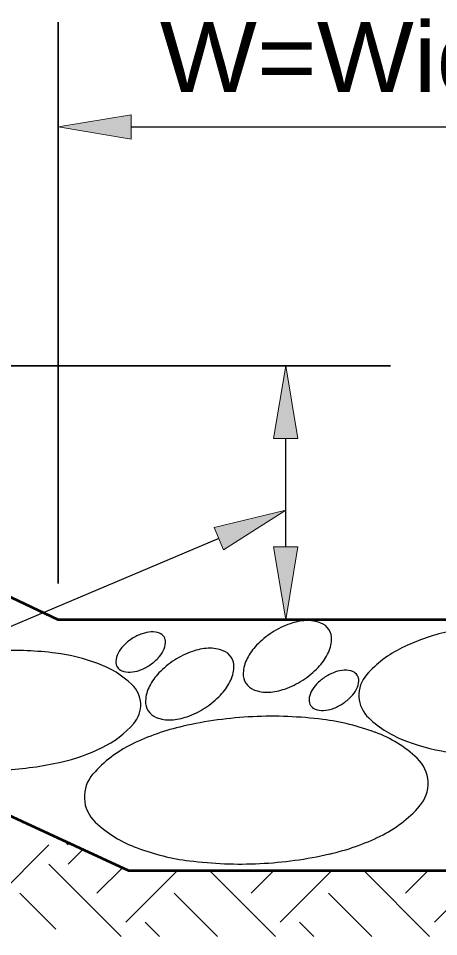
# Model space of a CAD drawing. Extents: x 72.6 to 107.3, y 36.1 to 58.1.
# Drawn here: x 96.33 to 97.053, y 37.866 to 39.443 of the extents above; entities that cross this region are included whole.
import ezdxf

# ---------------------------------------------------------------- set-up
doc = ezdxf.new("R2010")
doc.units = 0
doc.header["$LTSCALE"] = 0.053
for name, color, linetype, lineweight in [('1', 7, 'Continuous', 35), ('3', 7, 'Continuous', 13), ('4', 7, 'Continuous', 25), ('6', 7, 'Continuous', 13)]:
    doc.layers.add(name, color=color, linetype=linetype, lineweight=lineweight)

msp = doc.modelspace()

# ---------------------------------------------------------------- hatches: boundary and pattern name
at = {"layer": '1'}
for points in [[(96.52392, 39.2355), (96.52392, 39.27717), (96.39892, 39.25625), (96.39892, 39.25625)], [(96.81067, 38.72125), (96.769, 38.72125), (96.78983, 38.84625), (96.78983, 38.84625)], [(96.81067, 38.53542), (96.769, 38.53542), (96.78983, 38.41042), (96.78983, 38.41042)]]:
    msp.add_hatch(color=256, dxfattribs=at).paths.add_polyline_path(points)
at = {"layer": '3'}
msp.add_hatch(color=256, dxfattribs=at).paths.add_polyline_path([(96.66658, 38.56892), (96.68283, 38.53058), (96.78983, 38.59842), (96.78983, 38.59842)])

# ---------------------------------------------------------------- linework, layer by layer
at = {"layer": '1'}
for p, q in [((96.39892, 38.47283), (96.39892, 39.43633)), ((95.54108, 38.84625), (96.96983, 38.84625))]:
    msp.add_line(p, q, dxfattribs=at)
at = {"layer": '1', "lineweight": 25}
for p, q in [((96.52392, 39.25633), (97.34317, 39.25633)), ((96.78983, 38.53542), (96.78983, 38.72125)), ((96.28842, 37.92967), (96.38258, 38.02375)), ((96.28842, 37.92967), (96.38258, 38.02375)), ((96.41575, 38.02375), (96.40833, 38.03117)), ((96.41575, 38.02375), (96.40833, 38.03117)), ((96.41575, 37.99058), (96.44108, 38.016)), ((96.41575, 37.99058), (96.44108, 38.016)), ((96.50675, 37.86642), (96.38258, 37.99058)), ((96.50675, 37.86642), (96.38258, 37.99058)), ((96.46542, 37.94092), (96.50917, 37.98458)), ((96.46542, 37.94092), (96.50917, 37.98458)), ((96.51517, 37.89117), (96.60367, 37.97967)), ((96.51517, 37.89117), (96.60367, 37.97967)), ((96.77192, 37.86642), (96.65867, 37.97967)), ((96.77192, 37.86642), (96.65867, 37.97967)), ((96.73058, 37.94092), (96.76942, 37.97967)), ((96.73058, 37.94092), (96.76942, 37.97967)), ((96.78033, 37.89117), (96.86883, 37.97967)), ((96.78033, 37.89117), (96.86883, 37.97967)), ((97.03708, 37.86642), (96.92383, 37.97967)), ((97.03708, 37.86642), (96.92383, 37.97967)), ((96.99575, 37.94092), (97.03458, 37.97967)), ((96.99575, 37.94092), (97.03458, 37.97967)), ((97.0455, 37.89117), (97.134, 37.97967)), ((97.0455, 37.89117), (97.134, 37.97967)), ((96.3945, 37.87925), (96.33283, 37.94092)), ((96.3945, 37.87925), (96.33283, 37.94092)), ((96.6725, 37.86642), (96.598, 37.94092)), ((96.6725, 37.86642), (96.598, 37.94092)), ((96.93767, 37.86642), (96.86317, 37.94092)), ((96.93767, 37.86642), (96.86317, 37.94092)), ((96.57308, 37.86642), (96.54833, 37.89117)), ((96.57308, 37.86642), (96.54833, 37.89117)), ((96.83825, 37.86642), (96.8135, 37.89117)), ((96.83825, 37.86642), (96.8135, 37.89117))]:
    msp.add_line(p, q, dxfattribs=at)
at = {"layer": '1', "lineweight": 13}
msp.add_line((96.76808, 38.41042), (96.60983, 38.41042), dxfattribs=at)
for points in [[(96.52392, 39.2355), (96.52392, 39.27717), (96.39892, 39.25625), (96.39892, 39.25625)], [(96.81067, 38.72125), (96.769, 38.72125), (96.78983, 38.84625), (96.78983, 38.84625)], [(96.81067, 38.53542), (96.769, 38.53542), (96.78983, 38.41042), (96.78983, 38.41042)]]:
    msp.add_lwpolyline(points, close=True, dxfattribs=at)
at = {"layer": '1', "lineweight": 53}
for points in [[(94.3185, 38.997), (96.51967, 37.97967), (97.50133, 37.97967), (99.23892, 38.94783)], [(94.3185, 38.997), (96.51967, 37.97967), (97.50133, 37.97967), (99.23892, 38.94783)], [(98.934, 38.77792), (98.19075, 38.77792), (97.43333, 38.41042), (96.39892, 38.41042), (95.47858, 38.84625), (94.64467, 38.84625)]]:
    msp.add_lwpolyline(points, dxfattribs=at)
at = {"layer": '3'}
msp.add_lwpolyline([(96.66658, 38.56892), (96.68283, 38.53058), (96.78983, 38.59842), (96.78983, 38.59842)], close=True, dxfattribs=at)
at = {"layer": '3', "lineweight": 25}
msp.add_lwpolyline([(96.67475, 38.54975), (95.617, 38.10283), (95.20167, 38.10283)], dxfattribs=at)
at = {"layer": '4'}
for centre, radius, start, end in [((96.84646, 38.26402), 0.14793, 109.47631, 122.81482), ((96.82963, 38.31165), 0.09739, 93.02881, 109.47763), ((96.82776, 38.34713), 0.06186, 68.73244, 93.05444), ((96.83971, 38.37788), 0.02887, 32.82904, 68.71961), ((96.57082, 38.30801), 0.08321, 109.47631, 122.81482), ((96.56135, 38.3348), 0.05478, 93.02881, 109.47763), ((96.5603, 38.35476), 0.0348, 68.73244, 93.05444), ((96.56702, 38.37205), 0.01624, 32.82904, 68.71961), ((96.84646, 38.26397), 0.14796, 122.79611, 136.13461), ((96.83966, 38.37783), 0.02897, 356.96675, 32.85731), ((97.14917, 38.03333), 0.36555, 102.80576, 115.89117), ((96.57082, 38.30798), 0.08322, 122.79611, 136.13461), ((96.54854, 38.37303), 0.03477, 332.60197, 356.92397), ((96.567, 38.37203), 0.0163, 356.96675, 32.85731), ((96.80685, 38.37961), 0.06181, 332.60197, 356.92397), ((96.3234, 37.79777), 0.55983, 82.73383, 92.75763), ((96.3527, 38.02633), 0.32938, 69.67097, 82.75638), ((96.53261, 38.3369), 0.03483, 152.62903, 176.95103), ((96.55031, 38.32773), 0.05476, 136.15944, 152.60826), ((96.53069, 38.38228), 0.05489, 316.13726, 332.58607), ((96.67862, 38.21652), 0.14793, 109.47631, 122.81482), ((96.6618, 38.26415), 0.09739, 93.02881, 109.47763), ((96.65992, 38.29963), 0.06186, 68.73244, 93.05444), ((96.67188, 38.33038), 0.02887, 32.82904, 68.71961), ((96.80999, 38.29908), 0.09735, 136.15944, 152.60826), ((97.07402, 38.18806), 0.19354, 115.88116, 138.62437), ((96.51405, 38.33785), 0.01624, 176.85974, 212.7503), ((96.51028, 38.40182), 0.08314, 302.84584, 316.18434), ((96.67862, 38.21647), 0.14796, 122.79611, 136.13461), ((96.67183, 38.33033), 0.02897, 356.96675, 32.85731), ((96.77854, 38.3154), 0.06191, 152.62903, 176.95103), ((96.77511, 38.39607), 0.09757, 316.13726, 332.58607), ((96.4067, 38.17206), 0.174, 46.93966, 69.68286), ((96.51405, 38.33791), 0.01627, 212.92432, 248.81488), ((96.52085, 38.35515), 0.03481, 248.63072, 272.95272), ((96.51975, 38.37511), 0.05478, 273.02881, 289.47763), ((96.51028, 38.4019), 0.08321, 289.47631, 302.81482), ((96.63902, 38.33211), 0.06181, 332.60197, 356.92397), ((96.73883, 38.4308), 0.1478, 302.84584, 316.18434), ((96.90282, 38.24226), 0.08321, 109.47631, 122.81482), ((96.89335, 38.26905), 0.05478, 93.02881, 109.47763), ((96.8923, 38.28901), 0.0348, 68.73244, 93.05444), ((96.89902, 38.3063), 0.01624, 32.82904, 68.71961), ((96.64216, 38.25158), 0.09735, 136.15944, 152.60826), ((96.74554, 38.31708), 0.02888, 176.85974, 212.7503), ((96.73883, 38.43094), 0.14793, 289.47631, 302.81482), ((96.90282, 38.24223), 0.08322, 122.79611, 136.13461), ((96.88054, 38.30728), 0.03477, 332.60197, 356.92397), ((96.899, 38.30628), 0.0163, 356.96675, 32.85731), ((96.96879, 38.28076), 0.0533, 138.57538, 182.72304), ((96.49269, 38.26413), 0.04798, 2.71629, 46.86395), ((96.6107, 38.2679), 0.06191, 152.62903, 176.95103), ((96.60728, 38.34857), 0.09757, 316.13726, 332.58607), ((96.74554, 38.31718), 0.02893, 212.92432, 248.81488), ((96.75763, 38.34783), 0.06188, 248.63072, 272.95272), ((96.75566, 38.38332), 0.09739, 273.02881, 289.47763), ((96.88231, 38.26198), 0.05476, 136.15944, 152.60826), ((96.86269, 38.31653), 0.05489, 316.13726, 332.58607), ((96.571, 38.3833), 0.1478, 302.84584, 316.18434), ((96.84605, 38.2721), 0.01624, 176.85974, 212.7503), ((96.86461, 38.27115), 0.03483, 152.62903, 176.95103), ((96.84228, 38.33607), 0.08314, 302.84584, 316.18434), ((96.96879, 38.28083), 0.05335, 182.81358, 226.96124), ((96.49283, 38.26413), 0.04786, 318.6412, 2.78885), ((96.5777, 38.26958), 0.02888, 176.85974, 212.7503), ((96.571, 38.38344), 0.14793, 289.47631, 302.81482), ((96.84605, 38.27216), 0.01627, 212.92432, 248.81488), ((96.85285, 38.2894), 0.03481, 248.63072, 272.95272), ((96.85175, 38.30936), 0.05478, 273.02881, 289.47763), ((96.84228, 38.33615), 0.08321, 289.47631, 302.81482), ((96.5777, 38.26968), 0.02893, 212.92432, 248.81488), ((96.5898, 38.30033), 0.06188, 248.63072, 272.95272), ((96.58783, 38.33582), 0.09739, 273.02881, 289.47763), ((96.76625, 37.5535), 0.69124, 92.76039, 102.78419), ((96.76625, 37.5535), 0.69124, 92.76039, 102.78419), ((96.76625, 37.55358), 0.69114, 82.73383, 92.75763), ((96.76625, 37.55358), 0.69114, 82.73383, 92.75763), ((97.06442, 38.38306), 0.19334, 226.93966, 249.68286), ((96.39806, 38.34763), 0.17419, 295.88116, 318.62437), ((96.70333, 37.8315), 0.40617, 102.80576, 115.89117), ((96.70333, 37.8315), 0.40617, 102.80576, 115.89117), ((96.80242, 37.83575), 0.40665, 69.67097, 82.75638), ((96.80242, 37.83575), 0.40665, 69.67097, 82.75638), ((96.86908, 38.01567), 0.21482, 46.93966, 69.68286), ((96.86908, 38.01567), 0.21482, 46.93966, 69.68286), ((96.61983, 38.00342), 0.21505, 115.88116, 138.62437), ((96.61983, 38.00342), 0.21505, 115.88116, 138.62437), ((97.12442, 38.54461), 0.36566, 249.65869, 262.74409), ((96.33042, 38.48688), 0.329, 282.80576, 295.89117), ((96.27906, 38.71206), 0.55995, 272.79955, 282.82335), ((96.97525, 38.12933), 0.05923, 2.71629, 46.86395), ((96.97525, 38.12933), 0.05923, 2.71629, 46.86395), ((96.50292, 38.10642), 0.05923, 138.57538, 182.72304), ((96.50292, 38.10642), 0.05923, 138.57538, 182.72304), ((96.97542, 38.12933), 0.05908, 318.6412, 2.78885), ((96.97542, 38.12933), 0.05908, 318.6412, 2.78885), ((96.50292, 38.1065), 0.05928, 182.81358, 226.96124), ((96.50292, 38.1065), 0.05928, 182.81358, 226.96124), ((96.85842, 38.23242), 0.21505, 295.88116, 318.62437), ((96.85842, 38.23242), 0.21505, 295.88116, 318.62437), ((96.60917, 38.22008), 0.21482, 226.93966, 249.68286), ((96.60917, 38.22008), 0.21482, 226.93966, 249.68286), ((96.77492, 38.40433), 0.40617, 282.80576, 295.89117), ((96.77492, 38.40433), 0.40617, 282.80576, 295.89117), ((96.67583, 38.39958), 0.40629, 249.65869, 262.74409), ((96.67583, 38.39958), 0.40629, 249.65869, 262.74409), ((96.7115, 38.68233), 0.6913, 272.79955, 282.82335), ((96.7115, 38.68233), 0.6913, 272.79955, 282.82335), ((96.71192, 38.68267), 0.69162, 262.73539, 272.75919), ((96.71192, 38.68267), 0.69162, 262.73539, 272.75919)]:
    msp.add_arc(centre, radius, start, end, dxfattribs=at)
at = {"layer": '6'}
for p, q in [((96.78983, 38.84625), (96.78992, 38.84625)), ((96.39892, 38.41033), (96.399, 38.41033)), ((96.83058, 38.41042), (96.83067, 38.41042))]:
    msp.add_line(p, q, dxfattribs=at)

# ---------------------------------------------------------------- texts
at = {"layer": '1', "width": 1.1}
msp.add_text('W=Width', height=0.12, dxfattribs=at).set_placement((96.57358, 39.31633))

doc.saveas('drawing.dxf')
